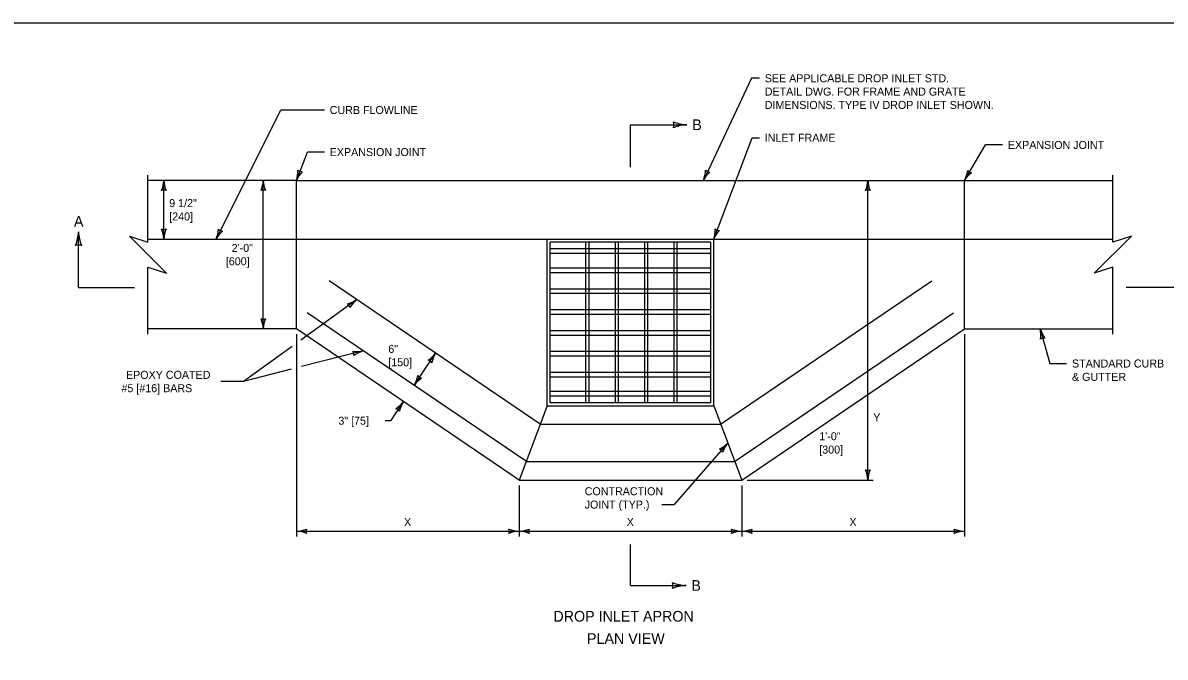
# Model space of a CAD drawing. Extents: x 49991.4 to 50048.3, y 49987.6 to 50018.3.
# Drawn here: x 50004.04 to 50012.6, y 49994.24 to 49999 of the extents above; entities that cross this region are included whole.
import ezdxf

# ---------------------------------------------------------------- set-up
doc = ezdxf.new("R2010")
doc.units = 0
for name, color, linetype in [('Level 1', 7, 'Continuous'), ('Level 2', 7, 'Continuous'), ('Level 3', 7, 'Continuous'), ('Level 4', 7, 'Continuous'), ('Level 6', 7, 'Continuous')]:
    doc.layers.add(name, color=color, linetype=linetype)

msp = doc.modelspace()

# ---------------------------------------------------------------- linework, layer by layer
at = {"layer": 'Level 1'}
for p, q in [((50006.0893, 49997.818), (50004.9765, 49997.818)), ((50006.0893, 49996.7052), (50006.0893, 49997.818)), ((50006.0893, 49997.818), (50011.0967, 49997.818)), ((50011.0967, 49996.7052), (50011.0967, 49997.818)), ((50011.0967, 49997.818), (50012.2094, 49997.818)), ((50004.9765, 49997.3769), (50012.2094, 49997.3769)), ((50007.9687, 49997.3769), (50009.2173, 49997.3769)), ((50007.9687, 49996.1281), (50007.9687, 49997.3769)), ((50009.2173, 49996.1281), (50009.2173, 49997.3769)), ((50009.1953, 49997.355), (50007.9906, 49997.355)), ((50007.9906, 49996.1502), (50007.9906, 49997.355)), ((50008.2601, 49997.3057), (50007.9906, 49997.3057)), ((50008.2601, 49996.1502), (50008.2601, 49997.355)), ((50008.2833, 49996.1502), (50008.2833, 49997.355)), ((50008.4803, 49997.3057), (50008.2833, 49997.3057)), ((50008.4803, 49996.1502), (50008.4803, 49997.355)), ((50008.5035, 49996.8124), (50008.5035, 49997.355)), ((50008.7005, 49997.3057), (50008.5035, 49997.3057)), ((50008.7005, 49996.1502), (50008.7005, 49997.355)), ((50008.7237, 49996.1502), (50008.7237, 49997.355)), ((50008.9208, 49997.3057), (50008.7237, 49997.3057)), ((50008.9208, 49996.1502), (50008.9208, 49997.355)), ((50008.944, 49996.1502), (50008.944, 49997.355)), ((50009.1953, 49997.3057), (50008.944, 49997.3057)), ((50009.1953, 49996.1502), (50009.1953, 49997.355)), ((50008.2601, 49997.271), (50007.9906, 49997.271)), ((50008.4803, 49997.271), (50008.2833, 49997.271)), ((50008.7005, 49997.271), (50008.5035, 49997.271)), ((50008.9208, 49997.271), (50008.7237, 49997.271)), ((50009.1953, 49997.271), (50008.944, 49997.271)), ((50008.2601, 49997.1601), (50007.9906, 49997.1601)), ((50008.2601, 49997.1254), (50007.9906, 49997.1254)), ((50008.4803, 49997.1601), (50008.2833, 49997.1601)), ((50008.4803, 49997.1254), (50008.2833, 49997.1254)), ((50008.7005, 49997.1601), (50008.5035, 49997.1601)), ((50008.7005, 49997.1254), (50008.5035, 49997.1254)), ((50008.9208, 49997.1601), (50008.7237, 49997.1601)), ((50008.9208, 49997.1254), (50008.7237, 49997.1254)), ((50009.1953, 49997.1601), (50008.944, 49997.1601)), ((50009.1953, 49997.1254), (50008.944, 49997.1254)), ((50008.2601, 49997.0037), (50007.9906, 49997.0037)), ((50008.2601, 49996.9689), (50007.9906, 49996.9689)), ((50008.4803, 49997.0037), (50008.2833, 49997.0037)), ((50008.4803, 49996.9689), (50008.2833, 49996.9689)), ((50008.7005, 49997.0037), (50008.5035, 49997.0037)), ((50008.7005, 49996.9689), (50008.5035, 49996.9689)), ((50008.9208, 49997.0037), (50008.7237, 49997.0037)), ((50008.9208, 49996.9689), (50008.7237, 49996.9689)), ((50009.1953, 49997.0037), (50008.944, 49997.0037)), ((50009.1953, 49996.9689), (50008.944, 49996.9689)), ((50008.2601, 49996.8472), (50007.9906, 49996.8472)), ((50008.2601, 49996.8124), (50007.9906, 49996.8124)), ((50008.4803, 49996.8472), (50008.2833, 49996.8472)), ((50008.4803, 49996.8124), (50008.2833, 49996.8124)), ((50008.7005, 49996.8472), (50008.5035, 49996.8472)), ((50008.5035, 49996.1502), (50008.5035, 49996.8124)), ((50008.7005, 49996.8124), (50008.5035, 49996.8124)), ((50008.9208, 49996.8472), (50008.7237, 49996.8472)), ((50008.9208, 49996.8124), (50008.7237, 49996.8124)), ((50009.1953, 49996.8472), (50008.944, 49996.8472)), ((50009.1953, 49996.8124), (50008.944, 49996.8124)), ((50006.0893, 49996.7052), (50004.9765, 49996.7052)), ((50007.7584, 49995.5717), (50006.0893, 49996.7052)), ((50008.2601, 49996.6907), (50007.9906, 49996.6907)), ((50008.4803, 49996.6907), (50008.2833, 49996.6907)), ((50008.7005, 49996.6907), (50008.5035, 49996.6907)), ((50008.9208, 49996.6907), (50008.7237, 49996.6907)), ((50009.1953, 49996.6907), (50008.944, 49996.6907)), ((50009.4275, 49995.5717), (50011.0967, 49996.7052)), ((50011.0967, 49996.7052), (50012.2094, 49996.7052)), ((50008.2601, 49996.6559), (50007.9906, 49996.6559)), ((50008.4803, 49996.6559), (50008.2833, 49996.6559)), ((50008.7005, 49996.6559), (50008.5035, 49996.6559)), ((50008.9208, 49996.6559), (50008.7237, 49996.6559)), ((50009.1953, 49996.6559), (50008.944, 49996.6559)), ((50008.2601, 49996.5342), (50007.9906, 49996.5342)), ((50008.4803, 49996.5342), (50008.2833, 49996.5342)), ((50008.7005, 49996.5342), (50008.5035, 49996.5342)), ((50008.9208, 49996.5342), (50008.7237, 49996.5342)), ((50009.1953, 49996.5342), (50008.944, 49996.5342)), ((50008.2601, 49996.4994), (50007.9906, 49996.4994)), ((50008.4803, 49996.4994), (50008.2833, 49996.4994)), ((50008.7005, 49996.4994), (50008.5035, 49996.4994)), ((50008.9208, 49996.4994), (50008.7237, 49996.4994)), ((50009.1953, 49996.4994), (50008.944, 49996.4994)), ((50008.2601, 49996.3777), (50007.9906, 49996.3777)), ((50008.4803, 49996.3777), (50008.2833, 49996.3777)), ((50008.7005, 49996.3777), (50008.5035, 49996.3777)), ((50008.9208, 49996.3777), (50008.7237, 49996.3777)), ((50009.1953, 49996.3777), (50008.944, 49996.3777)), ((50008.2601, 49996.343), (50007.9906, 49996.343)), ((50008.4803, 49996.343), (50008.2833, 49996.343)), ((50008.7005, 49996.343), (50008.5035, 49996.343)), ((50008.9208, 49996.343), (50008.7237, 49996.343)), ((50009.1953, 49996.343), (50008.944, 49996.343)), ((50008.2601, 49996.2342), (50007.9906, 49996.2342)), ((50008.2601, 49996.1995), (50007.9906, 49996.1995)), ((50008.4803, 49996.2342), (50008.2833, 49996.2342)), ((50008.4803, 49996.1995), (50008.2833, 49996.1995)), ((50008.7005, 49996.2342), (50008.5035, 49996.2342)), ((50008.7005, 49996.1995), (50008.5035, 49996.1995)), ((50008.9208, 49996.2342), (50008.7237, 49996.2342)), ((50008.9208, 49996.1995), (50008.7237, 49996.1995)), ((50009.1953, 49996.2342), (50008.944, 49996.2342)), ((50009.1953, 49996.1995), (50008.944, 49996.1995)), ((50007.9687, 49996.1281), (50007.7584, 49995.5717)), ((50007.9687, 49996.1281), (50009.2173, 49996.1281)), ((50009.1953, 49996.1502), (50007.9906, 49996.1502)), ((50009.2173, 49996.1281), (50009.4275, 49995.5717)), ((50007.7584, 49995.5717), (50009.4275, 49995.5717))]:
    msp.add_line(p, q, dxfattribs=at)
msp.add_lwpolyline([(49999.3835, 49998.9992), (50016.7501, 49998.9992), (50016.7501, 49987.7988), (49999.3835, 49987.7988)], close=True, dxfattribs=at)
at = {"layer": 'Level 3'}
for p, q in [((50009.4999, 49998.5837), (50009.1401, 49997.818)), ((50009.56, 49998.5837), (50009.4999, 49998.5837)), ((50005.487, 49997.3775), (50005.9731, 49998.3457)), ((50006.299, 49998.3457), (50005.9731, 49998.3457)), ((50009.2173, 49997.3769), (50009.5057, 49998.1377)), ((50009.5057, 49998.1377), (50009.5598, 49998.1377)), ((50011.0967, 49997.818), (50011.2553, 49998.0838)), ((50006.0893, 49997.818), (50006.1721, 49998.0304)), ((50006.299, 49998.0304), (50006.1721, 49998.0304)), ((50005.0961, 49997.3775), (50005.0961, 49997.818)), ((50005.841, 49996.7052), (50005.841, 49997.818)), ((50010.3732, 49995.5717), (50010.3732, 49997.818)), ((50006.543, 49996.9239), (50006.1217, 49996.6197)), ((50011.6642, 49996.7052), (50011.7363, 49996.4452)), ((50006.0893, 49996.6652), (50006.0893, 49995.1472)), ((50011.0967, 49996.6652), (50011.0967, 49995.1472)), ((50006.0568, 49996.5729), (50005.693, 49996.3102)), ((50006.5904, 49996.5405), (50006.128, 49996.4218)), ((50006.9716, 49996.2815), (50007.1326, 49996.5236)), ((50006.0505, 49996.402), (50005.693, 49996.3102)), ((50006.8912, 49996.1606), (50006.7952, 49996.0162)), ((50006.7952, 49996.0162), (50006.7552, 49996.0162)), ((50009.3224, 49995.85), (50008.9209, 49995.3875)), ((50007.7584, 49995.5317), (50007.7584, 49995.1472)), ((50009.4275, 49995.5317), (50009.4275, 49995.1472)), ((50009.4675, 49995.5717), (50010.4132, 49995.5717)), ((50008.8295, 49995.3875), (50008.9209, 49995.3875)), ((50006.0893, 49995.1872), (50007.7584, 49995.1872)), ((50007.7584, 49995.1872), (50009.4275, 49995.1872)), ((50009.4275, 49995.1872), (50011.0967, 49995.1872))]:
    msp.add_line(p, q, dxfattribs=at)
for points in [[(50011.3822, 49998.0838), (50011.3822, 49998.0838), (50011.2553, 49998.0838)], [(50011.7363, 49996.4452), (50011.8632, 49996.4452), (50011.8632, 49996.4452)], [(50005.693, 49996.3102), (50005.5221, 49996.3102), (50005.5221, 49996.3102)]]:
    msp.add_lwpolyline(points, dxfattribs=at)
for centre, radius, start, end in [((50005.8683, 49997.8919), 0.233, 341.51704, 0.76689), ((50006.1359, 49997.9374), 0.0548, 230.82855, 266.55091), ((50008.9246, 49997.9065), 0.233, 337.66355, 356.9134), ((50009.1947, 49997.934), 0.0548, 226.97506, 262.69742), ((50010.8909, 49997.9274), 0.233, 332.00488, 351.25473), ((50011.1624, 49997.9281), 0.0548, 221.31638, 257.03875), ((50004.874, 49997.8271), 0.2223, 337.45601, 357.63952), ((50005.3288, 49997.8295), 0.233, 182.82731, 202.07716), ((50005.6189, 49997.8271), 0.2223, 337.45601, 357.63952), ((50006.0737, 49997.8295), 0.233, 182.82731, 202.07716), ((50006.2929, 49997.7287), 0.2223, 136.14574, 156.32925), ((50009.3373, 49997.7153), 0.2223, 132.29225, 152.47576), ((50010.1511, 49997.8271), 0.2223, 337.45601, 357.63952), ((50010.606, 49997.8295), 0.233, 182.82731, 202.07716), ((50011.2827, 49997.6963), 0.2223, 126.63358, 146.81708), ((50005.0961, 49997.6898), 0.0548, 72.13882, 107.86118), ((50005.841, 49997.6898), 0.0548, 72.13882, 107.86118), ((50010.3732, 49997.6898), 0.0548, 72.13882, 107.86118), ((50005.0961, 49997.5057), 0.0548, 252.13882, 287.86118), ((50004.8634, 49997.366), 0.233, 2.82731, 22.07716), ((50005.3183, 49997.3684), 0.2223, 157.45601, 177.63952), ((50005.2739, 49997.4717), 0.233, 336.16588, 355.41573), ((50005.6814, 49997.2697), 0.2223, 130.79458, 150.97809), ((50005.5445, 49997.4921), 0.0548, 225.47739, 261.19975), ((50008.9956, 49997.4486), 0.233, 342.06557, 1.31542), ((50009.4217, 49997.2896), 0.2223, 136.69427, 156.87778), ((50009.2627, 49997.4968), 0.0548, 231.37708, 267.09944), ((50006.4204, 49997.1094), 0.2223, 283.28512, 303.46863), ((50006.4391, 49996.8489), 0.0548, 17.96793, 53.69029), ((50006.6886, 49996.742), 0.233, 128.65642, 147.90627), ((50005.841, 49996.8335), 0.0548, 252.13882, 287.86118), ((50005.6083, 49996.6937), 0.233, 2.82731, 22.07716), ((50006.0632, 49996.6961), 0.2223, 157.45601, 177.63952), ((50011.4477, 49996.6547), 0.2223, 352.95786, 13.14136), ((50011.8854, 49996.7785), 0.233, 198.32916, 217.57901), ((50011.6985, 49996.5817), 0.0548, 87.64066, 123.36302), ((50006.544, 49996.7579), 0.2223, 261.8458, 282.02931), ((50006.4662, 49996.5086), 0.0548, 356.52861, 32.25097), ((50006.6593, 49996.3179), 0.233, 107.2171, 126.46695), ((50006.9526, 49996.6542), 0.2223, 303.83894, 324.02245), ((50007.3327, 49996.4043), 0.233, 149.21024, 168.46009), ((50007.0615, 49996.4168), 0.0548, 38.52175, 74.24411), ((50006.7715, 49996.4008), 0.233, 329.21024, 348.46009), ((50007.0426, 49996.3883), 0.0548, 218.52175, 254.24411), ((50007.1515, 49996.1509), 0.2223, 123.83894, 144.02245), ((50006.7113, 49996.2912), 0.2223, 303.8388, 324.02231), ((50006.8202, 49996.0539), 0.0548, 38.52161, 74.24397), ((50007.0914, 49996.0414), 0.233, 149.2101, 168.45995), ((50009.1606, 49996.0025), 0.2223, 296.49713, 316.68064), ((50009.5057, 49995.7061), 0.233, 141.86843, 161.11828), ((50009.2383, 49995.7532), 0.0548, 31.17994, 66.9023), ((50010.3732, 49995.6999), 0.0548, 252.13882, 287.86118), ((50010.1405, 49995.5602), 0.233, 2.82731, 22.07716), ((50010.5954, 49995.5626), 0.2223, 157.45601, 177.63952), ((50006.0778, 49995.4199), 0.233, 272.82731, 292.07716), ((50006.0801, 49994.9651), 0.2223, 67.45601, 87.63952), ((50006.2175, 49995.1872), 0.0548, 162.13882, 197.86118), ((50007.7676, 49995.4094), 0.2223, 247.45601, 267.63952), ((50007.6302, 49995.1872), 0.0548, 342.13882, 17.86118), ((50007.7699, 49994.9545), 0.233, 92.82731, 112.07716), ((50007.7469, 49995.4199), 0.233, 272.82731, 292.07716), ((50007.7492, 49994.9651), 0.2223, 67.45601, 87.63952), ((50007.8866, 49995.1872), 0.0548, 162.13882, 197.86118), ((50009.4367, 49995.4094), 0.2223, 247.45601, 267.63952), ((50009.2993, 49995.1872), 0.0548, 342.13882, 17.86118), ((50009.439, 49994.9545), 0.233, 92.82731, 112.07716), ((50009.416, 49995.4199), 0.233, 272.82731, 292.07716), ((50009.4184, 49994.9651), 0.2223, 67.45601, 87.63952), ((50009.5557, 49995.1872), 0.0548, 162.13882, 197.86118), ((50011.1058, 49995.4094), 0.2223, 247.45601, 267.63952), ((50010.9685, 49995.1872), 0.0548, 342.13882, 17.86118), ((50011.1082, 49994.9545), 0.233, 92.82731, 112.07716)]:
    msp.add_arc(centre, radius, start, end, dxfattribs=at)
at = {"layer": 'Level 4'}
for p, q in [((50008.2833, 49997.3057), (50008.2601, 49997.3057)), ((50008.5035, 49997.3057), (50008.4803, 49997.3057)), ((50008.7237, 49997.3057), (50008.7005, 49997.3057)), ((50008.944, 49997.3057), (50008.9208, 49997.3057)), ((50008.2833, 49997.271), (50008.2601, 49997.271)), ((50008.5035, 49997.271), (50008.4803, 49997.271)), ((50008.7237, 49997.271), (50008.7005, 49997.271)), ((50008.944, 49997.271), (50008.9208, 49997.271)), ((50008.2833, 49997.1601), (50008.2601, 49997.1601)), ((50008.2833, 49997.1254), (50008.2601, 49997.1254)), ((50008.5035, 49997.1601), (50008.4803, 49997.1601)), ((50008.5035, 49997.1254), (50008.4803, 49997.1254)), ((50008.7237, 49997.1601), (50008.7005, 49997.1601)), ((50008.7237, 49997.1254), (50008.7005, 49997.1254)), ((50008.944, 49997.1601), (50008.9208, 49997.1601)), ((50008.944, 49997.1254), (50008.9208, 49997.1254)), ((50007.9237, 49995.9863), (50006.3341, 49997.0658)), ((50009.2691, 49995.991), (50010.8518, 49997.0658)), ((50008.2833, 49997.0037), (50008.2601, 49997.0037)), ((50008.2833, 49996.9689), (50008.2601, 49996.9689)), ((50008.5035, 49997.0037), (50008.4803, 49997.0037)), ((50008.5035, 49996.9689), (50008.4803, 49996.9689)), ((50008.7237, 49997.0037), (50008.7005, 49997.0037)), ((50008.7237, 49996.9689), (50008.7005, 49996.9689)), ((50008.944, 49997.0037), (50008.9208, 49997.0037)), ((50008.944, 49996.9689), (50008.9208, 49996.9689)), ((50007.8135, 49995.7098), (50006.1708, 49996.8254)), ((50008.2833, 49996.8472), (50008.2601, 49996.8472)), ((50008.2833, 49996.8124), (50008.2601, 49996.8124)), ((50008.5035, 49996.8472), (50008.4803, 49996.8472)), ((50008.5035, 49996.8124), (50008.4803, 49996.8124)), ((50008.7237, 49996.8472), (50008.7005, 49996.8472)), ((50008.7237, 49996.8124), (50008.7005, 49996.8124)), ((50008.944, 49996.8472), (50008.9208, 49996.8472)), ((50008.944, 49996.8124), (50008.9208, 49996.8124)), ((50009.3725, 49995.7098), (50011.0151, 49996.8254)), ((50008.2833, 49996.6907), (50008.2601, 49996.6907)), ((50008.5035, 49996.6907), (50008.4803, 49996.6907)), ((50008.7237, 49996.6907), (50008.7005, 49996.6907)), ((50008.944, 49996.6907), (50008.9208, 49996.6907)), ((50008.2833, 49996.6559), (50008.2601, 49996.6559)), ((50008.5035, 49996.6559), (50008.4803, 49996.6559)), ((50008.7237, 49996.6559), (50008.7005, 49996.6559)), ((50008.944, 49996.6559), (50008.9208, 49996.6559)), ((50008.2833, 49996.5342), (50008.2601, 49996.5342)), ((50008.5035, 49996.5342), (50008.4803, 49996.5342)), ((50008.7237, 49996.5342), (50008.7005, 49996.5342)), ((50008.944, 49996.5342), (50008.9208, 49996.5342)), ((50008.2833, 49996.4994), (50008.2601, 49996.4994)), ((50008.5035, 49996.4994), (50008.4803, 49996.4994)), ((50008.7237, 49996.4994), (50008.7005, 49996.4994)), ((50008.944, 49996.4994), (50008.9208, 49996.4994)), ((50008.2833, 49996.3777), (50008.2601, 49996.3777)), ((50008.5035, 49996.3777), (50008.4803, 49996.3777)), ((50008.7237, 49996.3777), (50008.7005, 49996.3777)), ((50008.944, 49996.3777), (50008.9208, 49996.3777)), ((50008.2833, 49996.343), (50008.2601, 49996.343)), ((50008.5035, 49996.343), (50008.4803, 49996.343)), ((50008.7237, 49996.343), (50008.7005, 49996.343)), ((50008.944, 49996.343), (50008.9208, 49996.343)), ((50008.2833, 49996.2342), (50008.2601, 49996.2342)), ((50008.2833, 49996.1995), (50008.2601, 49996.1995)), ((50008.5035, 49996.2342), (50008.4803, 49996.2342)), ((50008.5035, 49996.1995), (50008.4803, 49996.1995)), ((50008.7237, 49996.2342), (50008.7005, 49996.2342)), ((50008.7237, 49996.1995), (50008.7005, 49996.1995)), ((50008.944, 49996.2342), (50008.9208, 49996.2342)), ((50008.944, 49996.1995), (50008.9208, 49996.1995)), ((50007.9161, 49995.9892), (50009.2698, 49995.9892)), ((50007.811, 49995.7108), (50009.375, 49995.7108))]:
    msp.add_line(p, q, dxfattribs=at)
at = {"layer": 'Level 6'}
for p, q in [((50008.593, 49998.2353), (50009.0103, 49998.2353)), ((50008.593, 49997.918), (50008.593, 49998.2353)), ((50004.4563, 49997.014), (50004.4563, 49997.4313)), ((50004.4563, 49997.014), (50004.8765, 49997.014)), ((50012.7194, 49997.014), (50012.3094, 49997.014)), ((50008.593, 49994.7811), (50008.593, 49995.0872)), ((50008.593, 49994.7811), (50009.0103, 49994.7811))]:
    msp.add_line(p, q, dxfattribs=at)
for points in [[(50004.9765, 49996.6652), (50004.9765, 49997.1682), (50004.9763, 49997.1682), (50005.1156, 49997.1225), (50004.8374, 49997.4007), (50004.9765, 49997.3543), (50004.9765, 49997.858)], [(50012.2094, 49996.6652), (50012.2094, 49997.1682), (50012.2096, 49997.1682), (50012.0703, 49997.1225), (50012.3485, 49997.4007), (50012.2094, 49997.3543), (50012.2094, 49997.858)]]:
    msp.add_lwpolyline(points, dxfattribs=at)
for centre, radius, start, end in [((50009.0291, 49998.5315), 0.2964, 247.45605, 267.63955), ((50008.846, 49998.2353), 0.073, 342.13885, 17.86122), ((50009.0323, 49997.925), 0.3107, 92.82735, 112.0772), ((50004.1601, 49997.4435), 0.2964, 337.45601, 357.63952), ((50004.7666, 49997.4466), 0.3107, 182.82731, 202.07716), ((50004.4563, 49997.2603), 0.073, 72.13882, 107.86118), ((50009.0225, 49995.0773), 0.2964, 247.45657, 267.64008), ((50008.8393, 49994.7811), 0.073, 342.13938, 17.86174), ((50009.0256, 49994.4708), 0.3107, 92.82787, 112.07772)]:
    msp.add_arc(centre, radius, start, end, dxfattribs=at)

# ---------------------------------------------------------------- texts
at = {"layer": 'Level 2'}
for s, height, p in [('SEE APPLICABLE DROP INLET STD.', 0.06, (50009.6, 49998.5537)), ('DETAIL DWG. FOR FRAME AND GRATE', 0.06, (50009.6, 49998.4537)), ('DIMENSIONS. TYPE IV DROP INLET SHOWN.', 0.06, (50009.6, 49998.3537)), ('CURB FLOWLINE', 0.06, (50006.339, 49998.3157)), ('B', 0.08, (50009.0569, 49998.1953)), ('INLET FRAME', 0.06, (50009.5998, 49998.1077)), ('EXPANSION JOINT', 0.06, (50006.339, 49998.0004)), ('EXPANSION JOINT', 0.06, (50011.4222, 49998.0538)), ('9 1/2"', 0.06, (50005.1361, 49997.6178)), ('A', 0.08, (50004.422, 49997.4713)), ('[240]', 0.06, (50005.1361, 49997.5178)), ('2\'-0"', 0.06, (50005.6041, 49997.2816)), ('[600]', 0.06, (50005.5606, 49997.1816)), ('6"', 0.06, (50006.7783, 49996.5247)), ('[150]', 0.06, (50006.7783, 49996.4247)), ('STANDARD CURB', 0.06, (50011.9032, 49996.4152)), ('EPOXY COATED', 0.06, (50004.8121, 49996.3302)), ('& GUTTER', 0.06, (50011.9032, 49996.3152)), ('#5 [#16] BARS', 0.06, (50004.7781, 49996.2302)), ('3" [75]', 0.06, (50006.4041, 49995.9862)), ('Y', 0.06, (50010.4132, 49996.0105)), ('1\'-0"', 0.06, (50010.0089, 49995.8699)), ('[300]', 0.06, (50010.0089, 49995.7699)), ('CONTRACTION', 0.06, (50008.2504, 49995.4575)), ('JOINT (TYP.)', 0.06, (50008.2504, 49995.3575)), ('X', 0.06, (50006.8963, 49995.2272)), ('X', 0.06, (50008.5655, 49995.2272)), ('X', 0.06, (50010.2346, 49995.2272)), ('B', 0.08, (50009.0502, 49994.7411)), ('PLAN VIEW', 0.08, (50008.2677, 49994.3431))]:
    msp.add_text(s, height=height, dxfattribs=at).set_placement(p)
at = {"layer": 'Level 6'}
msp.add_text('DROP INLET APRON', height=0.08, dxfattribs=at).set_placement((50008.0159, 49994.5101))

doc.saveas('drawing.dxf')
